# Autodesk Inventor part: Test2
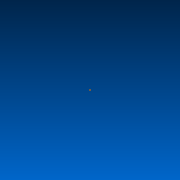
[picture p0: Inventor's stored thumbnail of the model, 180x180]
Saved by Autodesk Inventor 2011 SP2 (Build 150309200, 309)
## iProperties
Created: 2012-03
Part Number: Test2
Document SubType Name: Modeling
Designer: BH
Density: 1 g/cm^3
Author: BH
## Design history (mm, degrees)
sketch "Skizze1"
  geometry: L1 (0, 0)-(100, 0); L2 (100, 0)-(100, -40); L3 (100, -40)-(0, -40); L4 (0, -40)-(0, 0)
  constraints: 8 end point, 2 parallel, 1 horizontal, 1 perpendicular
  dimensions: "d0" = 100 distance of L2.end L3.end; "d1" = 40 distance of L1.end L2.end
extrude "Extrusion1" new body sketch "Skizze1" distance "d2" = 10; taper "d3" = 0 deg
sketch "Skizze2"
  geometry: C1 r 8.329 at (15.682, -21.158)
  constraints: 1 centre point
extrude "Extrusion2" cut sketch "Skizze2" distance "d4" = 10; taper "d5" = 0 deg
node "Volumenkörper1"
